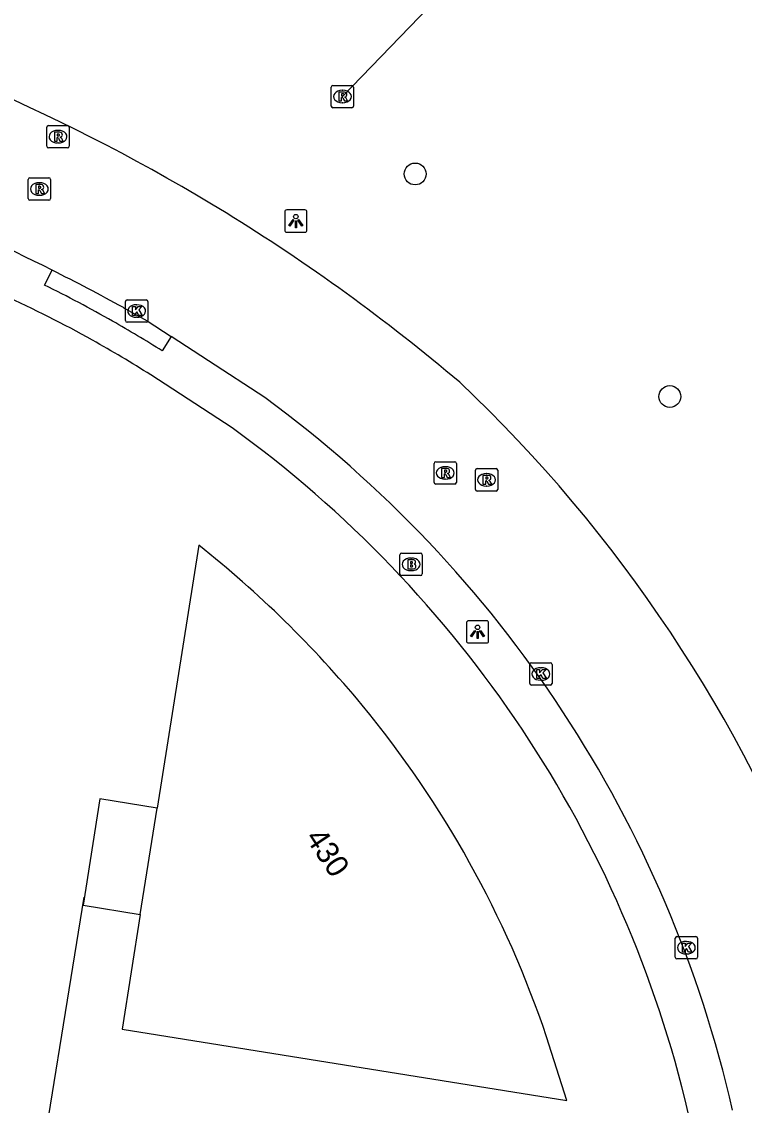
# Model space of a CAD drawing. Extents: x 154324 to 155743, y 382939 to 384183.
# Drawn here: x 155347.79 to 155380.14, y 383421.74 to 383470.22 of the extents above; entities that cross this region are included whole.
import ezdxf

# ---------------------------------------------------------------- set-up
doc = ezdxf.new("R2010")
doc.units = 0
for name, color, linetype in [('IMGEO_Boom', 7, 'Continuous'), ('IMGEO_Brandkraan', 7, 'Continuous'), ('IMGEO_Duiker', 7, 'Continuous'), ('IMGEO_Hek', 7, 'Continuous'), ('IMGEO_Kolk', 7, 'Continuous'), ('IMGEO_Lichtpunt', 7, 'Continuous'), ('IMGEO_Pand', 7, 'Continuous'), ('IMGEO_Pand_nummerreeks', 7, 'Continuous'), ('IMGEO_Rijbaan_lokaal_open', 7, 'Continuous'), ('IMGEO_Rioolput', 7, 'Continuous'), ('IMGEO_Voetpad_open', 7, 'Continuous')]:
    doc.layers.add(name, color=color, linetype=linetype)

msp = doc.modelspace()

# ---------------------------------------------------------------- linework, layer by layer
at = {"layer": 'IMGEO_Boom'}
for centre in [(155365.404, 383463.411), (155376.801, 383453.45)]:
    msp.add_circle(centre, 0.489, dxfattribs=at)
at = {"layer": 'IMGEO_Brandkraan'}
for p, q in [((155364.721, 383445.518), (155364.721, 383446.37)), ((155364.796, 383446.444), (155365.648, 383446.444)), ((155365.209, 383446.224), (155365.234, 383446.224)), ((155365.722, 383446.37), (155365.722, 383445.518)), ((155365.232, 383445.664), (155365.207, 383445.664)), ((155365.648, 383445.444), (155364.796, 383445.444))]:
    msp.add_line(p, q, dxfattribs=at)
for points in [[(155364.721, 383445.518), (155364.721, 383446.37)], [(155364.796, 383446.444), (155365.648, 383446.444)], [(155365.069, 383446.144), (155365.069, 383445.744), (155365.282, 383445.744)], [(155365.3, 383446.144), (155365.069, 383446.144)], [(155365.722, 383446.37), (155365.722, 383445.518)], [(155365.248, 383446.063), (155365.194, 383446.063), (155365.194, 383445.987)], [(155365.194, 383445.987), (155365.247, 383445.987)], [(155365.256, 383445.911), (155365.194, 383445.911), (155365.194, 383445.83)], [(155365.194, 383445.83), (155365.256, 383445.83)], [(155365.648, 383445.444), (155364.796, 383445.444)]]:
    msp.add_lwpolyline(points, dxfattribs=at)
for centre, radius, start, end in [((155364.798, 383446.368), 0.0765, 91.552, 178.448), ((155364.798, 383446.368), 0.0765, 91.552, 178.448), ((155365.304, 383445.999), 0.145, 59.4692, 91.5367), ((155365.329, 383446.046), 0.0922, 285.5137, 58.1501), ((155365.646, 383446.368), 0.0765, 1.552, 88.448), ((155365.646, 383446.368), 0.0765, 1.552, 88.448), ((155365.249, 383446.025), 0.0379, 267.8285, 90.9355), ((155365.257, 383445.87), 0.0404, 269.8759, 90.5077), ((155365.288, 383445.995), 0.251, 268.6676, 293.5347), ((155365.334, 383445.854), 0.105, 301.3115, 78.989), ((155364.798, 383445.52), 0.0765, 181.552, 268.448), ((155364.798, 383445.52), 0.0765, 181.552, 268.448), ((155365.646, 383445.52), 0.0765, 271.552, 358.448), ((155365.646, 383445.52), 0.0765, 271.552, 358.448)]:
    msp.add_arc(centre, radius, start, end, dxfattribs=at)
for centre, major_axis, ratio, start_param, end_param in [((155365.208, 383445.944), (-0.387, 0.002), 0.722429, 4.712389, 7.853982), ((155365.233, 383445.944), (-0.39, 0.002), 0.717154, 1.570796, 4.712389)]:
    msp.add_ellipse(centre, major_axis=major_axis, ratio=ratio, start_param=start_param, end_param=end_param, dxfattribs=at)
at = {"layer": 'IMGEO_Duiker'}
msp.add_lwpolyline([(155362.15, 383466.875), (155370.748, 383475.778)], dxfattribs=at)
at = {"layer": 'IMGEO_Hek'}
msp.add_lwpolyline([(155353.397, 383415.758), (155348.254, 383416.592), (155350.587, 383431.051)], dxfattribs=at)
at = {"layer": 'IMGEO_Kolk'}
for p, q in [((155352.514, 383457.777), (155353.366, 383457.777)), ((155352.439, 383456.851), (155352.439, 383457.703)), ((155352.927, 383457.557), (155352.952, 383457.557)), ((155353.44, 383457.703), (155353.44, 383456.851)), ((155353.366, 383456.777), (155352.514, 383456.777)), ((155352.95, 383456.997), (155352.925, 383456.997)), ((155370.531, 383440.613), (155370.531, 383441.465)), ((155370.606, 383441.539), (155371.458, 383441.539)), ((155371.019, 383441.319), (155371.044, 383441.319)), ((155371.532, 383441.465), (155371.532, 383440.613)), ((155371.458, 383440.539), (155370.606, 383440.539)), ((155371.042, 383440.759), (155371.017, 383440.759)), ((155377.041, 383428.365), (155377.041, 383429.217)), ((155377.116, 383429.291), (155377.968, 383429.291)), ((155378.042, 383429.217), (155378.042, 383428.365)), ((155377.529, 383429.071), (155377.554, 383429.071)), ((155377.968, 383428.291), (155377.116, 383428.291)), ((155377.552, 383428.511), (155377.527, 383428.511))]:
    msp.add_line(p, q, dxfattribs=at)
for points in [[(155352.514, 383457.777), (155353.366, 383457.777)], [(155352.439, 383456.851), (155352.439, 383457.703)], [(155352.76, 383457.477), (155352.883, 383457.477), (155352.883, 383457.326), (155353.013, 383457.477), (155353.177, 383457.477), (155353.031, 383457.326), (155353.184, 383457.077), (155353.032, 383457.077), (155352.947, 383457.241), (155352.883, 383457.174), (155352.883, 383457.077), (155352.76, 383457.077), (155352.76, 383457.477)], [(155353.44, 383457.703), (155353.44, 383456.851)], [(155353.366, 383456.777), (155352.514, 383456.777)], [(155370.531, 383440.613), (155370.531, 383441.465)], [(155370.606, 383441.539), (155371.458, 383441.539)], [(155371.532, 383441.465), (155371.532, 383440.613)], [(155370.852, 383441.239), (155370.975, 383441.239), (155370.975, 383441.088), (155371.105, 383441.239), (155371.269, 383441.239), (155371.123, 383441.088), (155371.276, 383440.839), (155371.124, 383440.839), (155371.039, 383441.003), (155370.975, 383440.936), (155370.975, 383440.839), (155370.852, 383440.839), (155370.852, 383441.239)], [(155371.458, 383440.539), (155370.606, 383440.539)], [(155377.041, 383428.365), (155377.041, 383429.217)], [(155377.116, 383429.291), (155377.968, 383429.291)], [(155378.042, 383429.217), (155378.042, 383428.365)], [(155377.362, 383428.991), (155377.485, 383428.991), (155377.485, 383428.84), (155377.615, 383428.991), (155377.779, 383428.991), (155377.633, 383428.84), (155377.786, 383428.591), (155377.634, 383428.591), (155377.549, 383428.755), (155377.485, 383428.688), (155377.485, 383428.591), (155377.362, 383428.591), (155377.362, 383428.991)], [(155377.968, 383428.291), (155377.116, 383428.291)]]:
    msp.add_lwpolyline(points, dxfattribs=at)
for centre, start, end in [((155352.516, 383457.701), 91.552, 178.448), ((155352.516, 383457.701), 91.552, 178.448), ((155353.364, 383457.701), 1.552, 88.448), ((155353.364, 383457.701), 1.552, 88.448), ((155352.516, 383456.853), 181.552, 268.448), ((155352.516, 383456.853), 181.552, 268.448), ((155353.364, 383456.853), 271.552, 358.448), ((155353.364, 383456.853), 271.552, 358.448), ((155370.608, 383441.463), 91.552, 178.448), ((155370.608, 383441.463), 91.552, 178.448), ((155371.456, 383441.463), 1.552, 88.448), ((155371.456, 383441.463), 1.552, 88.448), ((155370.608, 383440.615), 181.552, 268.448), ((155370.608, 383440.615), 181.552, 268.448), ((155371.456, 383440.615), 271.552, 358.448), ((155371.456, 383440.615), 271.552, 358.448), ((155377.118, 383429.215), 91.552, 178.448), ((155377.118, 383429.215), 91.552, 178.448), ((155377.966, 383429.215), 1.552, 88.448), ((155377.966, 383429.215), 1.552, 88.448), ((155377.118, 383428.367), 181.552, 268.448), ((155377.118, 383428.367), 181.552, 268.448), ((155377.966, 383428.367), 271.552, 358.448), ((155377.966, 383428.367), 271.552, 358.448)]:
    msp.add_arc(centre, 0.0765, start, end, dxfattribs=at)
for centre, major_axis, ratio, start_param, end_param in [((155352.926, 383457.277), (-0.387, 0.002), 0.722429, 4.712389, 7.853982), ((155352.951, 383457.277), (-0.39, 0.002), 0.717154, 1.570796, 4.712389), ((155371.018, 383441.039), (-0.387, 0.002), 0.722429, 4.712389, 7.853982), ((155371.043, 383441.039), (-0.39, 0.002), 0.717154, 1.570796, 4.712389), ((155377.528, 383428.791), (-0.387, 0.002), 0.722429, 4.712389, 7.853982), ((155377.553, 383428.791), (-0.39, 0.002), 0.717154, 1.570796, 4.712389)]:
    msp.add_ellipse(centre, major_axis=major_axis, ratio=ratio, start_param=start_param, end_param=end_param, dxfattribs=at)
at = {"layer": 'IMGEO_Lichtpunt'}
for p, q in [((155359.565, 383461.704), (155359.565, 383460.897)), ((155359.565, 383461.704), (155359.565, 383460.897)), ((155360.467, 383461.799), (155359.659, 383461.799)), ((155360.467, 383461.799), (155359.659, 383461.799)), ((155360.561, 383460.897), (155360.561, 383461.704)), ((155360.561, 383460.897), (155360.561, 383461.704)), ((155359.659, 383460.803), (155360.467, 383460.803)), ((155359.659, 383460.803), (155360.467, 383460.803)), ((155367.697, 383443.326), (155367.697, 383442.519)), ((155367.697, 383443.326), (155367.697, 383442.519)), ((155368.599, 383443.421), (155367.791, 383443.421)), ((155368.599, 383443.421), (155367.791, 383443.421)), ((155368.693, 383442.519), (155368.693, 383443.326)), ((155368.693, 383442.519), (155368.693, 383443.326)), ((155367.791, 383442.425), (155368.599, 383442.425)), ((155367.791, 383442.425), (155368.599, 383442.425))]:
    msp.add_line(p, q, dxfattribs=at)
for points in [[(155359.939, 383461.368), (155359.978, 383461.34), (155359.79, 383461.078), (155359.752, 383461.105), (155359.939, 383461.368)], [(155360.041, 383461.32), (155360.088, 383461.32), (155360.088, 383460.998), (155360.041, 383460.998), (155360.041, 383461.32)], [(155360.151, 383461.34), (155360.189, 383461.367), (155360.376, 383461.105), (155360.337, 383461.077), (155360.151, 383461.34)], [(155368.071, 383442.99), (155368.11, 383442.962), (155367.922, 383442.7), (155367.884, 383442.727), (155368.071, 383442.99)], [(155368.173, 383442.942), (155368.22, 383442.942), (155368.22, 383442.62), (155368.173, 383442.62), (155368.173, 383442.942)], [(155368.283, 383442.962), (155368.321, 383442.989), (155368.508, 383442.727), (155368.469, 383442.699), (155368.283, 383442.962)]]:
    msp.add_lwpolyline(points, dxfattribs=at)
for centre in [(155360.064, 383461.502), (155368.196, 383443.124)]:
    msp.add_circle(centre, 0.0994, dxfattribs=at)
for centre, start, end in [((155359.659, 383461.704), 90, 180), ((155359.659, 383461.704), 90, 180), ((155360.467, 383461.704), 0, 90), ((155360.467, 383461.704), 0, 90), ((155359.659, 383460.897), 180, 270), ((155359.659, 383460.897), 180, 270), ((155360.467, 383460.897), 270, 0), ((155360.467, 383460.897), 270, 360), ((155367.791, 383443.326), 90, 180), ((155367.791, 383443.326), 90, 180), ((155368.599, 383443.326), 0, 90), ((155368.599, 383443.326), 0, 90), ((155367.791, 383442.519), 180, 270), ((155367.791, 383442.519), 180, 270), ((155368.599, 383442.519), 270, 0), ((155368.599, 383442.519), 270, 360)]:
    msp.add_arc(centre, 0.0946, start, end, dxfattribs=at)
at = {"layer": 'IMGEO_Pand'}
for points in [[(155355.715, 383446.803), (155353.852, 383435.041)], [(155353.852, 383435.041), (155351.285, 383435.448), (155350.549, 383430.699), (155353.096, 383430.27)], [(155353.096, 383430.27), (155353.852, 383435.041)], [(155353.096, 383430.27), (155352.285, 383425.153), (155372.19, 383421.959), (155371.286, 383424.798)]]:
    msp.add_lwpolyline(points, dxfattribs=at)
for centre, radius, start, end in [((155325.018, 383408.09), 49.406, 39.6858, 51.5876), ((155326.8, 383409.792), 46.949, 18.6408, 39.4769)]:
    msp.add_arc(centre, radius, start, end, dxfattribs=at)
at = {"layer": 'IMGEO_Rijbaan_lokaal_open'}
for points in [[(155352.346, 383457.432), (155352.439, 383457.379), (155353.405, 383456.833), (155354.49, 383456.132)], [(155358.672, 383453.408), (155356.158, 383455.053), (155354.49, 383456.132)]]:
    msp.add_lwpolyline(points, dxfattribs=at)
for centre, radius, start, end in [((155312.033, 383388.632), 85.735, 58.41362, 74.83277), ((155302.55, 383366.417), 103.746, 63.30392, 67.32185), ((155311.996, 383388.605), 85.777, 49.76722, 58.40243), ((155303.395, 383367.999), 101.953, 61.30576, 63.32842), ((155322.678, 383406.824), 65.069, 20.763, 46.58434), ((155326.335, 383409.358), 54.645, 12.8574, 53.718)]:
    msp.add_arc(centre, radius, start, end, dxfattribs=at)
at = {"layer": 'IMGEO_Rioolput'}
for p, q in [((155361.649, 383466.449), (155361.649, 383467.301)), ((155361.724, 383467.375), (155362.576, 383467.375)), ((155362.137, 383467.155), (155362.162, 383467.155)), ((155362.65, 383467.301), (155362.65, 383466.449)), ((155362.16, 383466.595), (155362.135, 383466.595)), ((155362.576, 383466.375), (155361.724, 383466.375)), ((155348.918, 383464.652), (155348.918, 383465.504)), ((155348.993, 383465.578), (155349.845, 383465.578)), ((155349.919, 383465.504), (155349.919, 383464.652)), ((155349.406, 383465.358), (155349.431, 383465.358)), ((155349.845, 383464.578), (155348.993, 383464.578)), ((155349.429, 383464.798), (155349.404, 383464.798)), ((155348.084, 383462.312), (155348.084, 383463.164)), ((155348.159, 383463.238), (155349.011, 383463.238)), ((155349.085, 383463.164), (155349.085, 383462.312)), ((155348.572, 383463.018), (155348.597, 383463.018)), ((155349.011, 383462.238), (155348.159, 383462.238)), ((155348.595, 383462.458), (155348.57, 383462.458)), ((155366.326, 383450.534), (155367.178, 383450.534)), ((155366.251, 383449.608), (155366.251, 383450.46)), ((155366.739, 383450.314), (155366.764, 383450.314)), ((155367.252, 383450.46), (155367.252, 383449.608)), ((155368.099, 383449.299), (155368.099, 383450.151)), ((155368.174, 383450.225), (155369.026, 383450.225)), ((155368.587, 383450.005), (155368.612, 383450.005)), ((155369.1, 383450.151), (155369.1, 383449.299)), ((155367.178, 383449.534), (155366.326, 383449.534)), ((155366.762, 383449.754), (155366.737, 383449.754)), ((155369.026, 383449.225), (155368.174, 383449.225)), ((155368.61, 383449.445), (155368.585, 383449.445))]:
    msp.add_line(p, q, dxfattribs=at)
for points in [[(155361.649, 383466.449), (155361.649, 383467.301)], [(155361.724, 383467.375), (155362.576, 383467.375)], [(155362.238, 383467.073), (155361.986, 383467.075), (155361.986, 383466.675)], [(155362.164, 383466.994), (155362.11, 383466.994), (155362.11, 383466.913)], [(155362.65, 383467.301), (155362.65, 383466.449)], [(155361.986, 383466.675), (155362.11, 383466.675), (155362.11, 383466.837), (155362.121, 383466.837)], [(155362.11, 383466.913), (155362.162, 383466.913)], [(155362.168, 383466.808), (155362.239, 383466.675), (155362.379, 383466.675), (155362.314, 383466.801)], [(155362.576, 383466.375), (155361.724, 383466.375)], [(155348.918, 383464.652), (155348.918, 383465.504)], [(155348.993, 383465.578), (155349.845, 383465.578)], [(155349.919, 383465.504), (155349.919, 383464.652)], [(155349.507, 383465.276), (155349.255, 383465.278), (155349.255, 383464.878)], [(155349.255, 383464.878), (155349.379, 383464.878), (155349.379, 383465.04), (155349.39, 383465.04)], [(155349.433, 383465.197), (155349.379, 383465.197), (155349.379, 383465.116)], [(155349.379, 383465.116), (155349.431, 383465.116)], [(155349.845, 383464.578), (155348.993, 383464.578)], [(155349.437, 383465.011), (155349.508, 383464.878), (155349.648, 383464.878), (155349.583, 383465.004)], [(155348.084, 383462.312), (155348.084, 383463.164)], [(155348.159, 383463.238), (155349.011, 383463.238)], [(155349.085, 383463.164), (155349.085, 383462.312)], [(155348.673, 383462.936), (155348.421, 383462.938), (155348.421, 383462.538)], [(155348.421, 383462.538), (155348.545, 383462.538), (155348.545, 383462.7), (155348.556, 383462.7)], [(155348.599, 383462.857), (155348.545, 383462.857), (155348.545, 383462.776)], [(155348.545, 383462.776), (155348.597, 383462.776)], [(155348.603, 383462.671), (155348.674, 383462.538), (155348.814, 383462.538), (155348.749, 383462.664)], [(155349.011, 383462.238), (155348.159, 383462.238)], [(155366.326, 383450.534), (155367.178, 383450.534)], [(155366.251, 383449.608), (155366.251, 383450.46)], [(155366.84, 383450.232), (155366.588, 383450.234), (155366.588, 383449.834)], [(155366.588, 383449.834), (155366.712, 383449.834), (155366.712, 383449.996), (155366.723, 383449.996)], [(155366.766, 383450.153), (155366.712, 383450.153), (155366.712, 383450.072)], [(155366.712, 383450.072), (155366.764, 383450.072)], [(155367.252, 383450.46), (155367.252, 383449.608)], [(155368.099, 383449.299), (155368.099, 383450.151)], [(155368.174, 383450.225), (155369.026, 383450.225)], [(155369.1, 383450.151), (155369.1, 383449.299)], [(155367.178, 383449.534), (155366.326, 383449.534)], [(155366.77, 383449.967), (155366.841, 383449.834), (155366.981, 383449.834), (155366.916, 383449.96)], [(155368.688, 383449.923), (155368.436, 383449.925), (155368.436, 383449.525)], [(155368.436, 383449.525), (155368.56, 383449.525), (155368.56, 383449.687), (155368.571, 383449.687)], [(155368.614, 383449.844), (155368.56, 383449.844), (155368.56, 383449.763)], [(155368.56, 383449.763), (155368.612, 383449.763)], [(155368.618, 383449.658), (155368.689, 383449.525), (155368.829, 383449.525), (155368.764, 383449.651)], [(155369.026, 383449.225), (155368.174, 383449.225)]]:
    msp.add_lwpolyline(points, dxfattribs=at)
for centre, radius, start, end in [((155361.726, 383467.299), 0.0765, 91.552, 178.448), ((155361.726, 383467.299), 0.0765, 91.552, 178.448), ((155362.17, 383466.898), 0.0964, 77.0061, 93.1865), ((155362.184, 383466.955), 0.0378, 276.6634, 79.6772), ((155362.237, 383466.963), 0.109, 350.3612, 89.416), ((155362.574, 383467.299), 0.0765, 1.552, 88.448), ((155362.574, 383467.299), 0.0765, 1.552, 88.448), ((155362.12, 383466.784), 0.0533, 26.0293, 88.6989), ((155362.146, 383467.102), 0.19, 274.7715, 282.9687), ((155362.235, 383466.963), 0.112, 277.5842, 350.9817), ((155362.219, 383466.748), 0.108, 29.5134, 73.7905), ((155361.726, 383466.451), 0.0765, 181.552, 268.448), ((155361.726, 383466.451), 0.0765, 181.552, 268.448), ((155362.574, 383466.451), 0.0765, 271.552, 358.448), ((155362.574, 383466.451), 0.0765, 271.552, 358.448), ((155348.995, 383465.502), 0.0765, 91.552, 178.448), ((155348.995, 383465.502), 0.0765, 91.552, 178.448), ((155349.843, 383465.502), 0.0765, 1.552, 88.448), ((155349.843, 383465.502), 0.0765, 1.552, 88.448), ((155349.389, 383464.987), 0.0533, 26.0293, 88.6989), ((155349.415, 383465.305), 0.19, 274.7715, 282.9687), ((155349.439, 383465.101), 0.0964, 77.0061, 93.1865), ((155349.453, 383465.158), 0.0378, 276.6634, 79.6772), ((155349.506, 383465.166), 0.109, 350.3612, 89.416), ((155349.504, 383465.166), 0.112, 277.5842, 350.9817), ((155349.488, 383464.951), 0.108, 29.5134, 73.7905), ((155348.995, 383464.654), 0.0765, 181.552, 268.448), ((155348.995, 383464.654), 0.0765, 181.552, 268.448), ((155349.843, 383464.654), 0.0765, 271.552, 358.448), ((155349.843, 383464.654), 0.0765, 271.552, 358.448), ((155348.161, 383463.162), 0.0765, 91.552, 178.448), ((155348.161, 383463.162), 0.0765, 91.552, 178.448), ((155349.009, 383463.162), 0.0765, 1.552, 88.448), ((155349.009, 383463.162), 0.0765, 1.552, 88.448), ((155348.555, 383462.647), 0.0533, 26.0293, 88.6989), ((155348.581, 383462.965), 0.19, 274.7715, 282.9687), ((155348.605, 383462.761), 0.0964, 77.0061, 93.1865), ((155348.619, 383462.818), 0.0378, 276.6634, 79.6772), ((155348.672, 383462.826), 0.109, 350.3612, 89.416), ((155348.67, 383462.826), 0.112, 277.5842, 350.9817), ((155348.654, 383462.611), 0.108, 29.5134, 73.7905), ((155348.161, 383462.314), 0.0765, 181.552, 268.448), ((155348.161, 383462.314), 0.0765, 181.552, 268.448), ((155349.009, 383462.314), 0.0765, 271.552, 358.448), ((155349.009, 383462.314), 0.0765, 271.552, 358.448), ((155366.328, 383450.458), 0.0765, 91.552, 178.448), ((155366.328, 383450.458), 0.0765, 91.552, 178.448), ((155367.176, 383450.458), 0.0765, 1.552, 88.448), ((155367.176, 383450.458), 0.0765, 1.552, 88.448), ((155366.722, 383449.943), 0.0533, 26.0293, 88.6989), ((155366.748, 383450.261), 0.19, 274.7715, 282.9687), ((155366.772, 383450.057), 0.0964, 77.0061, 93.1865), ((155366.786, 383450.114), 0.0378, 276.6634, 79.6772), ((155366.839, 383450.122), 0.109, 350.3612, 89.416), ((155366.837, 383450.122), 0.112, 277.5842, 350.9817), ((155366.821, 383449.907), 0.108, 29.5134, 73.7905), ((155368.176, 383450.149), 0.0765, 91.552, 178.448), ((155368.176, 383450.149), 0.0765, 91.552, 178.448), ((155369.024, 383450.149), 0.0765, 1.552, 88.448), ((155369.024, 383450.149), 0.0765, 1.552, 88.448), ((155366.328, 383449.61), 0.0765, 181.552, 268.448), ((155366.328, 383449.61), 0.0765, 181.552, 268.448), ((155367.176, 383449.61), 0.0765, 271.552, 358.448), ((155367.176, 383449.61), 0.0765, 271.552, 358.448), ((155368.57, 383449.634), 0.0533, 26.0293, 88.6989), ((155368.596, 383449.952), 0.19, 274.7715, 282.9687), ((155368.62, 383449.748), 0.0964, 77.0061, 93.1865), ((155368.634, 383449.805), 0.0378, 276.6634, 79.6772), ((155368.687, 383449.813), 0.109, 350.3612, 89.416), ((155368.685, 383449.813), 0.112, 277.5842, 350.9817), ((155368.669, 383449.598), 0.108, 29.5134, 73.7905), ((155368.176, 383449.301), 0.0765, 181.552, 268.448), ((155368.176, 383449.301), 0.0765, 181.552, 268.448), ((155369.024, 383449.301), 0.0765, 271.552, 358.448), ((155369.024, 383449.301), 0.0765, 271.552, 358.448)]:
    msp.add_arc(centre, radius, start, end, dxfattribs=at)
for centre, major_axis, ratio, start_param, end_param in [((155362.136, 383466.875), (-0.387, 0.002), 0.722429, 4.712389, 7.853982), ((155362.161, 383466.875), (-0.39, 0.002), 0.717154, 1.570796, 4.712389), ((155349.405, 383465.078), (-0.387, 0.002), 0.722429, 4.712389, 7.853982), ((155349.43, 383465.078), (-0.39, 0.002), 0.717154, 1.570796, 4.712389), ((155348.571, 383462.738), (-0.387, 0.002), 0.722429, 4.712389, 7.853982), ((155348.596, 383462.738), (-0.39, 0.002), 0.717154, 1.570796, 4.712389), ((155366.738, 383450.034), (-0.387, 0.002), 0.722429, 4.712389, 7.853982), ((155366.763, 383450.034), (-0.39, 0.002), 0.717154, 1.570796, 4.712389), ((155368.586, 383449.725), (-0.387, 0.002), 0.722429, 4.712389, 7.853982), ((155368.611, 383449.725), (-0.39, 0.002), 0.717154, 1.570796, 4.712389)]:
    msp.add_ellipse(centre, major_axis=major_axis, ratio=ratio, start_param=start_param, end_param=end_param, dxfattribs=at)
at = {"layer": 'IMGEO_Voetpad_open'}
for points in [[(155348.816, 383458.437), (155349.159, 383459.104)], [(155354.49, 383456.132), (155354.081, 383455.494)], [(155357.216, 383452.045), (155353.569, 383454.42)]]:
    msp.add_lwpolyline(points, dxfattribs=at)
for centre, radius, start, end in [((155324.295, 383408.44), 55.687, 60.3311, 63.8743), ((155325.371, 383410.082), 52.545, 60.8513, 65.7078), ((155324.714, 383409.024), 54.972, 57.7088, 60.4092), ((155325.24, 383409.862), 52.801, 57.5525, 60.844), ((155326.36, 383409.367), 52.663, 13.2166, 54.1334)]:
    msp.add_arc(centre, radius, start, end, dxfattribs=at)

# ---------------------------------------------------------------- texts
at = {"layer": 'IMGEO_Pand_nummerreeks'}
msp.add_text('430', height=1, rotation=303.5522, dxfattribs=at).set_placement((155360.46, 383433.712))

doc.saveas('drawing.dxf')
